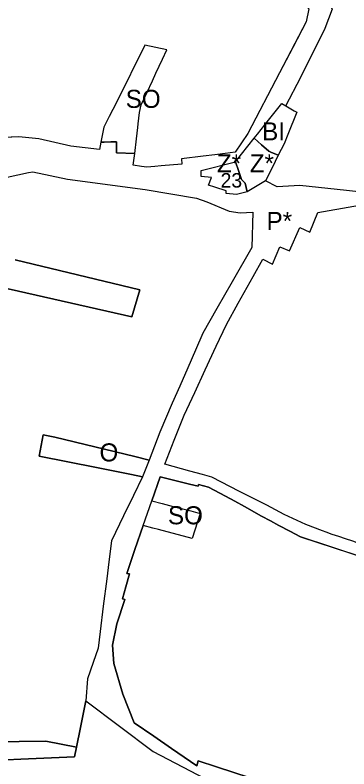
# Model space of a CAD drawing. Extents: x -521621 to -516769, y -1190068 to -1185078.
# Drawn here: x -518790.4 to -518605.8, y -1187170.7 to -1186753.4 of the extents above; entities that cross this region are included whole.
import ezdxf

# ---------------------------------------------------------------- set-up
doc = ezdxf.new("R2010")
doc.units = 0
for name, color, linetype in [('bydleni_s', 7, 'Continuous'), ('fpl_id', 7, 'Continuous'), ('s_zelen_n', 7, 'Continuous'), ('s_zelen_s', 7, 'Continuous'), ('sm_vyuziti_s', 7, 'Continuous'), ('v_infrastr_s', 7, 'Continuous')]:
    doc.layers.add(name, color=color, linetype=linetype)

msp = doc.modelspace()

# ---------------------------------------------------------------- linework, layer by layer
at = {"layer": 'bydleni_s'}
for p, q in [((-518788.4, -1186820.82), (-518801.54, -1186821.32)), ((-518777.28, -1186821.83), (-518788.4, -1186820.82)), ((-518759.68, -1186825.87), (-518777.28, -1186821.83)), ((-518686.42, -1186831.53), (-518698.46, -1186833.03)), ((-518717.57, -1186837.58), (-518720.44, -1186837.13)), ((-518659.46, -1186882.03), (-518670.36, -1186901.02)), ((-518667.01, -1186912.93), (-518658.69, -1186898.02)), ((-518670.36, -1186901.02), (-518678.86, -1186915.81)), ((-518673.52, -1186924.6), (-518667.01, -1186912.93)), ((-518678.86, -1186915.81), (-518686.69, -1186929.46)), ((-518679.19, -1186936.77), (-518673.52, -1186924.6)), ((-518686.69, -1186929.46), (-518690.74, -1186938.82)), ((-518685.25, -1186949.78), (-518679.19, -1186936.77)), ((-518690.74, -1186938.82), (-518694.98, -1186948.6)), ((-518694.98, -1186948.6), (-518699.38, -1186958.77)), ((-518691.07, -1186962.27), (-518685.25, -1186949.78)), ((-518699.38, -1186958.77), (-518703.48, -1186968.25)), ((-518696.93, -1186974.84), (-518691.07, -1186962.27)), ((-518702.44, -1186988.76), (-518696.93, -1186974.84)), ((-518720.01, -1187009.01), (-518725.03, -1187019.41)), ((-518725.03, -1187019.41), (-518730.41, -1187030.55)), ((-518730.41, -1187030.55), (-518734.94, -1187039.92)), ((-518734.94, -1187039.92), (-518737.14, -1187044.48)), ((-518751.25, -1187132.97), (-518754.24, -1187147.83)), ((-518754.24, -1187147.83), (-518756.41, -1187158.62))]:
    msp.add_line(p, q, dxfattribs=at)
for points in [[(-518628.01, -1186749.96), (-518629.41, -1186757.16), (-518636.76, -1186771.23)], [(-518718.67, -1186770.1), (-518734.44, -1186801.73)], [(-518706.54, -1186772.57), (-518718.67, -1186770.1)], [(-518636.76, -1186771.23), (-518644.11, -1186785.29)], [(-518712.52, -1186785.51), (-518708.96, -1186777.8), (-518706.54, -1186772.57)], [(-518714.46, -1186789.69), (-518712.52, -1186785.51)], [(-518644.11, -1186785.29), (-518661.66, -1186818.88), (-518668.73, -1186829.32), (-518674.33, -1186830.02)], [(-518720.64, -1186803.05), (-518714.46, -1186789.69)], [(-518734.44, -1186801.73), (-518738.34, -1186809.56), (-518741.3, -1186815.5), (-518743.09, -1186823.68)], [(-518724.31, -1186830.04), (-518723.33, -1186821.89), (-518722.57, -1186815.55), (-518722.34, -1186813.63), (-518721.59, -1186807.33), (-518720.64, -1186803.05)], [(-518650.27, -1186811.57), (-518642.95, -1186802.36), (-518640.78, -1186803.61), (-518636.04, -1186806.34), (-518634.57, -1186807.18), (-518639.56, -1186819.46)], [(-518650.13, -1186828.8), (-518654.11, -1186825.17), (-518658.15, -1186821.48), (-518656.39, -1186819.27), (-518650.27, -1186811.57)], [(-518639.56, -1186819.46), (-518641.7, -1186824.74)], [(-518743.09, -1186823.68), (-518743.85, -1186827.81), (-518759.68, -1186825.87)], [(-518641.7, -1186824.74), (-518644.86, -1186830.91), (-518648.97, -1186829.27), (-518650.13, -1186828.8)], [(-518720.44, -1186837.13), (-518725.07, -1186836.4), (-518724.31, -1186830.04)], [(-518698.46, -1186833.03), (-518698.29, -1186835.98), (-518709.58, -1186836.92)], [(-518674.33, -1186830.02), (-518679.92, -1186830.72), (-518686.42, -1186831.53)], [(-518709.58, -1186836.92), (-518713.09, -1186837.21), (-518717.57, -1186837.58)], [(-518802.69, -1186855.15), (-518794.9, -1186843.06), (-518783.09, -1186840.61), (-518780.65, -1186840.1), (-518771.03, -1186842.13), (-518761.45, -1186844.15)], [(-518761.45, -1186844.15), (-518718.5, -1186849.96), (-518690.12, -1186854.76), (-518684.4, -1186856.78), (-518672.1, -1186861.91), (-518665.95, -1186862.92), (-518658.96, -1186862.42), (-518659.46, -1186882.03)], [(-518627.41, -1186873.54), (-518623.03, -1186862.59), (-518603.14, -1186859.16)], [(-518638.7, -1186883.84), (-518633.03, -1186870.95), (-518627.41, -1186873.54)], [(-518648.08, -1186891.27), (-518643.96, -1186881.69), (-518638.7, -1186883.84)], [(-518725.89, -1186920.49), (-518721.5, -1186905.52), (-518790.45, -1186888.88)], [(-518658.69, -1186898.02), (-518653.4, -1186888.53), (-518648.08, -1186891.27)], [(-518798.31, -1186903.93), (-518725.89, -1186920.49)], [(-518703.48, -1186968.25), (-518710.46, -1186984.36)], [(-518716.22, -1186999.84), (-518724.24, -1186997.81), (-518768.4, -1186986.98), (-518774.98, -1186985.72), (-518777.21, -1186997.59), (-518745.38, -1187003.94)], [(-518710.46, -1186984.36), (-518716.22, -1186999.84)], [(-518681.62, -1187009.26), (-518686.82, -1187007.82), (-518693.71, -1187005.91), (-518707.69, -1187002.04), (-518702.44, -1186988.76)], [(-518745.38, -1187003.94), (-518726.05, -1187007.8)], [(-518726.05, -1187007.8), (-518720.01, -1187009.01)], [(-518580.04, -1187059.55), (-518632.58, -1187042.27), (-518632.58, -1187042.27), (-518638.52, -1187039.09), (-518644.54, -1187035.88), (-518649.25, -1187033.36), (-518654.08, -1187030.77), (-518663.63, -1187025.39), (-518668.87, -1187022.44), (-518674.08, -1187019.66), (-518683.39, -1187014.7), (-518688.96, -1187013.18), (-518689.21, -1187014.19), (-518693.96, -1187013.02), (-518710.22, -1187009), (-518714.83, -1187022.37)], [(-518651.21, -1187024.72), (-518666.25, -1187017.07), (-518681.62, -1187009.26)], [(-518714.83, -1187022.37), (-518709.18, -1187023.83), (-518702.98, -1187025.43), (-518694.73, -1187027.56), (-518693.28, -1187027.93), (-518688.08, -1187029.28), (-518691.05, -1187038.52), (-518692.56, -1187043.23), (-518711.14, -1187038.21), (-518714.28, -1187037.36), (-518719.52, -1187035.95)], [(-518641.69, -1187029.91), (-518646.4, -1187027.34), (-518651.21, -1187024.72)], [(-518629.7, -1187035.37), (-518641.69, -1187029.91)], [(-518719.52, -1187035.95), (-518724.14, -1187049.33), (-518728.7, -1187062.54), (-518727.18, -1187062.79), (-518729.23, -1187070.02), (-518731.1, -1187076.58), (-518729.84, -1187076.96), (-518734.14, -1187090.5)], [(-518618.47, -1187039.72), (-518620.49, -1187038.94), (-518629.7, -1187035.37)], [(-518607.65, -1187043.39), (-518611.46, -1187042.1), (-518615.01, -1187040.89), (-518618.47, -1187039.72)], [(-518737.14, -1187044.48), (-518738.58, -1187056.03)], [(-518582.5, -1187051.91), (-518593.56, -1187048.16), (-518594.75, -1187047.76), (-518600.34, -1187045.87), (-518603.73, -1187044.72), (-518607.65, -1187043.39)], [(-518738.58, -1187056.03), (-518739.78, -1187065.59), (-518741.66, -1187080.64), (-518743.41, -1187094.66), (-518744.55, -1187103.82), (-518747.29, -1187111.74), (-518750.42, -1187120.79)], [(-518734.14, -1187090.5), (-518736.54, -1187102.27), (-518735.79, -1187112.4), (-518730.85, -1187129.35), (-518724.52, -1187145.17)], [(-518750.42, -1187120.79), (-518751.25, -1187132.97)], [(-518724.52, -1187145.17), (-518713.71, -1187152.65), (-518704.01, -1187159.37), (-518689.97, -1187169.09), (-518689.21, -1187166.31), (-518679.09, -1187169.6), (-518578.03, -1187202.6)], [(-518756.41, -1187158.62), (-518773.51, -1187155.4), (-518832.43, -1187156.14)]]:
    msp.add_lwpolyline(points, dxfattribs=at)
at = {"layer": 's_zelen_n'}
msp.add_lwpolyline([(-518687.61, -1186839.39), (-518668.54, -1186834.67), (-518666.92, -1186839.49), (-518665.28, -1186844.36), (-518663.22, -1186846.36), (-518662.02, -1186851.18), (-518665.01, -1186851.93), (-518668.04, -1186852.69), (-518673.76, -1186852.08), (-518673.76, -1186850.63), (-518680.05, -1186848.65), (-518683.49, -1186847.57), (-518681.84, -1186843.35), (-518687.46, -1186842.75)], close=True, dxfattribs=at)
at = {"layer": 's_zelen_s'}
for points in [[(-518665.19, -1186830.42), (-518658.15, -1186821.48), (-518654.11, -1186825.17), (-518650.13, -1186828.8), (-518648.97, -1186829.27), (-518644.86, -1186830.91), (-518648.33, -1186837.98), (-518651.88, -1186845.21)], [(-518651.88, -1186845.21), (-518662.02, -1186851.18), (-518663.22, -1186846.36), (-518665.28, -1186844.36), (-518666.92, -1186839.49), (-518668.54, -1186834.67), (-518665.19, -1186830.42)], [(-518787.19, -1187165.35), (-518842.9, -1187167.84), (-518893.85, -1187160.56), (-518902.51, -1187159.27), (-518902.05, -1187148.12)], [(-518832.43, -1187156.14), (-518773.51, -1187155.4), (-518756.41, -1187158.62), (-518757.5, -1187164.02), (-518787.19, -1187165.35)]]:
    msp.add_lwpolyline(points, dxfattribs=at)
at = {"layer": 'sm_vyuziti_s'}
for points in [[(-518718.67, -1186770.1), (-518734.44, -1186801.73)], [(-518708.96, -1186777.8), (-518706.54, -1186772.57), (-518718.67, -1186770.1)], [(-518712.52, -1186785.51), (-518708.96, -1186777.8)], [(-518720.64, -1186803.05), (-518714.46, -1186789.69), (-518712.52, -1186785.51)], [(-518734.44, -1186801.73), (-518738.34, -1186809.56), (-518741.3, -1186815.5), (-518743.09, -1186823.68), (-518741.15, -1186823.68), (-518737.42, -1186823.47), (-518734.41, -1186823.47), (-518734.33, -1186829.73), (-518724.31, -1186830.04), (-518723.33, -1186821.89), (-518722.57, -1186815.55), (-518722.34, -1186813.63), (-518721.59, -1186807.33), (-518720.64, -1186803.05)], [(-518790.45, -1186888.88), (-518721.5, -1186905.52), (-518725.89, -1186920.49)], [(-518725.89, -1186920.49), (-518798.31, -1186903.93)]]:
    msp.add_lwpolyline(points, dxfattribs=at)
msp.add_lwpolyline([(-518719.52, -1187035.95), (-518714.83, -1187022.37), (-518709.18, -1187023.83), (-518702.98, -1187025.43), (-518694.73, -1187027.56), (-518693.28, -1187027.93), (-518688.08, -1187029.28), (-518691.05, -1187038.52), (-518692.56, -1187043.23), (-518711.14, -1187038.21), (-518714.28, -1187037.36)], close=True, dxfattribs=at)
at = {"layer": 'v_infrastr_s'}
for p, q in [((-518658.96, -1186862.42), (-518659.46, -1186882.03)), ((-518659.46, -1186882.03), (-518670.36, -1186901.02)), ((-518658.69, -1186898.02), (-518653.4, -1186888.53)), ((-518667.01, -1186912.93), (-518658.69, -1186898.02)), ((-518670.36, -1186901.02), (-518678.86, -1186915.81)), ((-518673.52, -1186924.6), (-518667.01, -1186912.93)), ((-518678.86, -1186915.81), (-518686.69, -1186929.46)), ((-518679.19, -1186936.77), (-518673.52, -1186924.6)), ((-518686.69, -1186929.46), (-518690.74, -1186938.82)), ((-518685.25, -1186949.78), (-518679.19, -1186936.77)), ((-518690.74, -1186938.82), (-518694.98, -1186948.6)), ((-518694.98, -1186948.6), (-518699.38, -1186958.77)), ((-518691.07, -1186962.27), (-518685.25, -1186949.78)), ((-518699.38, -1186958.77), (-518703.48, -1186968.25)), ((-518696.93, -1186974.84), (-518691.07, -1186962.27)), ((-518703.48, -1186968.25), (-518710.46, -1186984.36)), ((-518702.44, -1186988.76), (-518696.93, -1186974.84)), ((-518710.46, -1186984.36), (-518716.22, -1186999.84)), ((-518707.69, -1187002.04), (-518702.44, -1186988.76)), ((-518716.22, -1186999.84), (-518720.01, -1187009.01)), ((-518693.71, -1187005.91), (-518707.69, -1187002.04)), ((-518720.01, -1187009.01), (-518725.03, -1187019.41)), ((-518714.83, -1187022.37), (-518710.22, -1187009)), ((-518710.22, -1187009), (-518693.96, -1187013.02)), ((-518686.82, -1187007.82), (-518693.71, -1187005.91)), ((-518681.62, -1187009.26), (-518686.82, -1187007.82)), ((-518693.96, -1187013.02), (-518689.21, -1187014.19)), ((-518689.21, -1187014.19), (-518688.96, -1187013.18)), ((-518688.96, -1187013.18), (-518683.39, -1187014.7)), ((-518725.03, -1187019.41), (-518730.41, -1187030.55)), ((-518719.52, -1187035.95), (-518714.83, -1187022.37)), ((-518730.41, -1187030.55), (-518734.94, -1187039.92)), ((-518724.14, -1187049.33), (-518719.52, -1187035.95)), ((-518734.94, -1187039.92), (-518737.14, -1187044.48)), ((-518632.58, -1187042.27), (-518580.04, -1187059.55)), ((-518611.46, -1187042.1), (-518615.01, -1187040.89)), ((-518737.14, -1187044.48), (-518738.58, -1187056.03)), ((-518728.7, -1187062.54), (-518724.14, -1187049.33)), ((-518738.58, -1187056.03), (-518739.78, -1187065.59)), ((-518729.23, -1187070.02), (-518727.18, -1187062.79)), ((-518727.18, -1187062.79), (-518728.7, -1187062.54)), ((-518739.78, -1187065.59), (-518741.66, -1187080.64)), ((-518731.1, -1187076.58), (-518729.23, -1187070.02)), ((-518734.14, -1187090.5), (-518729.84, -1187076.96)), ((-518729.84, -1187076.96), (-518731.1, -1187076.58)), ((-518741.66, -1187080.64), (-518743.41, -1187094.66)), ((-518736.54, -1187102.27), (-518734.14, -1187090.5)), ((-518743.41, -1187094.66), (-518744.55, -1187103.82)), ((-518744.55, -1187103.82), (-518747.29, -1187111.74)), ((-518735.79, -1187112.4), (-518736.54, -1187102.27)), ((-518747.29, -1187111.74), (-518750.42, -1187120.79)), ((-518730.85, -1187129.35), (-518735.79, -1187112.4)), ((-518750.42, -1187120.79), (-518751.25, -1187132.97)), ((-518724.52, -1187145.17), (-518730.85, -1187129.35)), ((-518751.25, -1187132.97), (-518714.03, -1187161.03)), ((-518713.71, -1187152.65), (-518724.52, -1187145.17)), ((-518704.01, -1187159.37), (-518713.71, -1187152.65)), ((-518689.97, -1187169.09), (-518704.01, -1187159.37)), ((-518714.03, -1187161.03), (-518685.48, -1187176.02)), ((-518689.21, -1187166.31), (-518689.97, -1187169.09)), ((-518679.09, -1187169.6), (-518689.21, -1187166.31)), ((-518679.09, -1187169.6), (-518679.09, -1187169.6))]:
    msp.add_line(p, q, dxfattribs=at)
for points in [[(-518632.48, -1186787.66), (-518618.97, -1186760.67), (-518614.96, -1186749.91), (-518623.97, -1186738.16), (-518631.26, -1186717.27), (-518633.09, -1186702.14), (-518633.8, -1186696.27), (-518634.51, -1186690.41), (-518635.18, -1186684.81), (-518635.86, -1186679.21), (-518636.46, -1186674.19), (-518637.07, -1186669.18), (-518637.97, -1186660.69), (-518638.87, -1186652.2), (-518641.42, -1186652.16), (-518643.96, -1186652.12), (-518646.98, -1186651.61), (-518645.02, -1186670.08), (-518643.8, -1186680.17), (-518642.45, -1186691.37), (-518641.03, -1186703.1), (-518639.2, -1186718.23), (-518642.77, -1186724.91), (-518645.14, -1186728.45)], [(-518645.14, -1186728.45), (-518647.52, -1186731.99), (-518644.54, -1186733.73), (-518642.07, -1186735.17), (-518628.01, -1186749.96), (-518629.41, -1186757.16), (-518644.11, -1186785.29)], [(-518644.11, -1186785.29), (-518661.66, -1186818.88), (-518668.73, -1186829.32), (-518674.33, -1186830.02), (-518679.92, -1186830.72), (-518686.42, -1186831.53), (-518698.46, -1186833.03), (-518698.29, -1186835.98), (-518709.58, -1186836.92), (-518713.09, -1186837.21), (-518717.57, -1186837.58), (-518720.44, -1186837.13), (-518725.07, -1186836.4), (-518724.31, -1186830.04), (-518734.33, -1186829.73), (-518734.41, -1186823.47), (-518737.42, -1186823.47), (-518741.15, -1186823.68), (-518743.09, -1186823.68), (-518743.85, -1186827.81), (-518759.68, -1186825.87), (-518777.28, -1186821.83), (-518788.4, -1186820.82), (-518801.54, -1186821.32)], [(-518640.78, -1186803.61), (-518632.48, -1186787.66)], [(-518651.88, -1186845.21), (-518662.02, -1186851.18), (-518665.01, -1186851.93), (-518668.04, -1186852.69), (-518673.76, -1186852.08), (-518673.76, -1186850.63), (-518680.05, -1186848.65), (-518683.49, -1186847.57), (-518681.84, -1186843.35), (-518687.46, -1186842.75), (-518687.61, -1186839.39), (-518668.54, -1186834.67), (-518665.19, -1186830.42), (-518658.15, -1186821.48), (-518656.39, -1186819.27), (-518650.27, -1186811.57), (-518642.95, -1186802.36), (-518640.78, -1186803.61)], [(-518794.9, -1186843.06), (-518783.09, -1186840.61), (-518780.65, -1186840.1)], [(-518780.65, -1186840.1), (-518771.03, -1186842.13), (-518761.45, -1186844.15), (-518718.5, -1186849.96), (-518690.12, -1186854.76), (-518684.4, -1186856.78), (-518672.1, -1186861.91), (-518665.95, -1186862.92), (-518658.96, -1186862.42)], [(-518645.57, -1186848.44), (-518651.88, -1186845.21)], [(-518632.89, -1186847.81), (-518645.57, -1186848.44)], [(-518442.24, -1186920.02), (-518447.29, -1186917.52), (-518471.11, -1186905.76), (-518496.37, -1186893.28), (-518515.56, -1186883.8), (-518521.93, -1186880.66), (-518547.66, -1186867.89), (-518552.08, -1186866.83), (-518549.49, -1186859.73), (-518582.03, -1186853.35), (-518607.21, -1186850.56), (-518632.89, -1186847.81)], [(-518653.4, -1186888.53), (-518648.08, -1186891.27), (-518643.96, -1186881.69), (-518638.7, -1186883.84), (-518633.03, -1186870.95), (-518627.41, -1186873.54), (-518623.03, -1186862.59), (-518603.14, -1186859.16), (-518600.85, -1186858.76), (-518587.77, -1186865.41)], [(-518745.38, -1187003.94), (-518777.21, -1186997.59), (-518774.98, -1186985.72), (-518768.4, -1186986.98), (-518724.24, -1186997.81), (-518716.22, -1186999.84), (-518720.01, -1187009.01), (-518726.05, -1187007.8)], [(-518726.05, -1187007.8), (-518745.38, -1187003.94)], [(-518620.49, -1187038.94), (-518629.7, -1187035.37), (-518641.69, -1187029.91), (-518646.4, -1187027.34), (-518651.21, -1187024.72), (-518666.25, -1187017.07), (-518681.62, -1187009.26)], [(-518683.39, -1187014.7), (-518674.08, -1187019.66), (-518668.87, -1187022.44), (-518663.63, -1187025.39), (-518654.08, -1187030.77), (-518649.25, -1187033.36), (-518644.54, -1187035.88), (-518638.52, -1187039.09), (-518632.58, -1187042.27)], [(-518615.01, -1187040.89), (-518618.47, -1187039.72), (-518620.49, -1187038.94)], [(-518603.73, -1187044.72), (-518607.65, -1187043.39), (-518611.46, -1187042.1)], [(-518754.24, -1187147.83), (-518751.25, -1187132.97)], [(-518751.25, -1187132.97), (-518714.03, -1187161.03)], [(-518756.41, -1187158.62), (-518754.24, -1187147.83)], [(-518757.5, -1187164.02), (-518756.41, -1187158.62)], [(-518714.03, -1187161.03), (-518685.48, -1187176.02)], [(-518842.9, -1187167.84), (-518787.19, -1187165.35)], [(-518787.19, -1187165.35), (-518757.5, -1187164.02)], [(-518448.05, -1187243.78), (-518451.33, -1187242.83), (-518454.9, -1187241.8), (-518460.05, -1187240.32), (-518463.62, -1187239.29), (-518470.62, -1187237.28), (-518472.37, -1187236.78), (-518473.22, -1187236.53), (-518534.43, -1187216.02), (-518545.72, -1187212.65), (-518576.26, -1187203.11), (-518578.03, -1187202.6), (-518679.09, -1187169.6)]]:
    msp.add_lwpolyline(points, dxfattribs=at)

# ---------------------------------------------------------------- texts
at = {"layer": 'bydleni_s'}
msp.add_text('BI', height=10, dxfattribs=at).set_placement((-518653.79, -1186822.75))
at = {"layer": 'fpl_id'}
msp.add_text('23', height=8, dxfattribs=at).set_placement((-518676.77, -1186848.86))
at = {"layer": 's_zelen_n'}
msp.add_text('Z*', height=10, dxfattribs=at).set_placement((-518678.85, -1186840.46))
at = {"layer": 's_zelen_s'}
msp.add_text('Z*', height=10, dxfattribs=at).set_placement((-518660.64, -1186840.41))
at = {"layer": 'sm_vyuziti_s'}
for p in [(-518729.27, -1186804.75), (-518705.89, -1187035.31)]:
    msp.add_text('SO', height=10, dxfattribs=at).set_placement(p)
at = {"layer": 'v_infrastr_s'}
for s, p in [('P*', (-518651.34, -1186872.36)), ('O', (-518743.74, -1187000.49))]:
    msp.add_text(s, height=10, dxfattribs=at).set_placement(p)

doc.saveas('drawing.dxf')
